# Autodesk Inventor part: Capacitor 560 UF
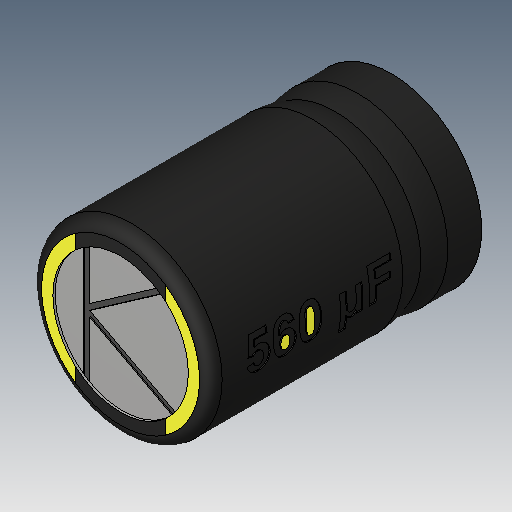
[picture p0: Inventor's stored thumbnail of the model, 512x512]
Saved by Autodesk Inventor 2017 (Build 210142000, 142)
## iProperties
Created: 2005-12
Part Number: Capacitor 560 UF
Material: Generic
Document SubType Name: Modeling
Designer: DanielSeverino
Density: 1 g/cm^3
Appearance: Default
Author: DanielSeverino
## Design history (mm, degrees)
feature "Solid1"
body "Solid2"
